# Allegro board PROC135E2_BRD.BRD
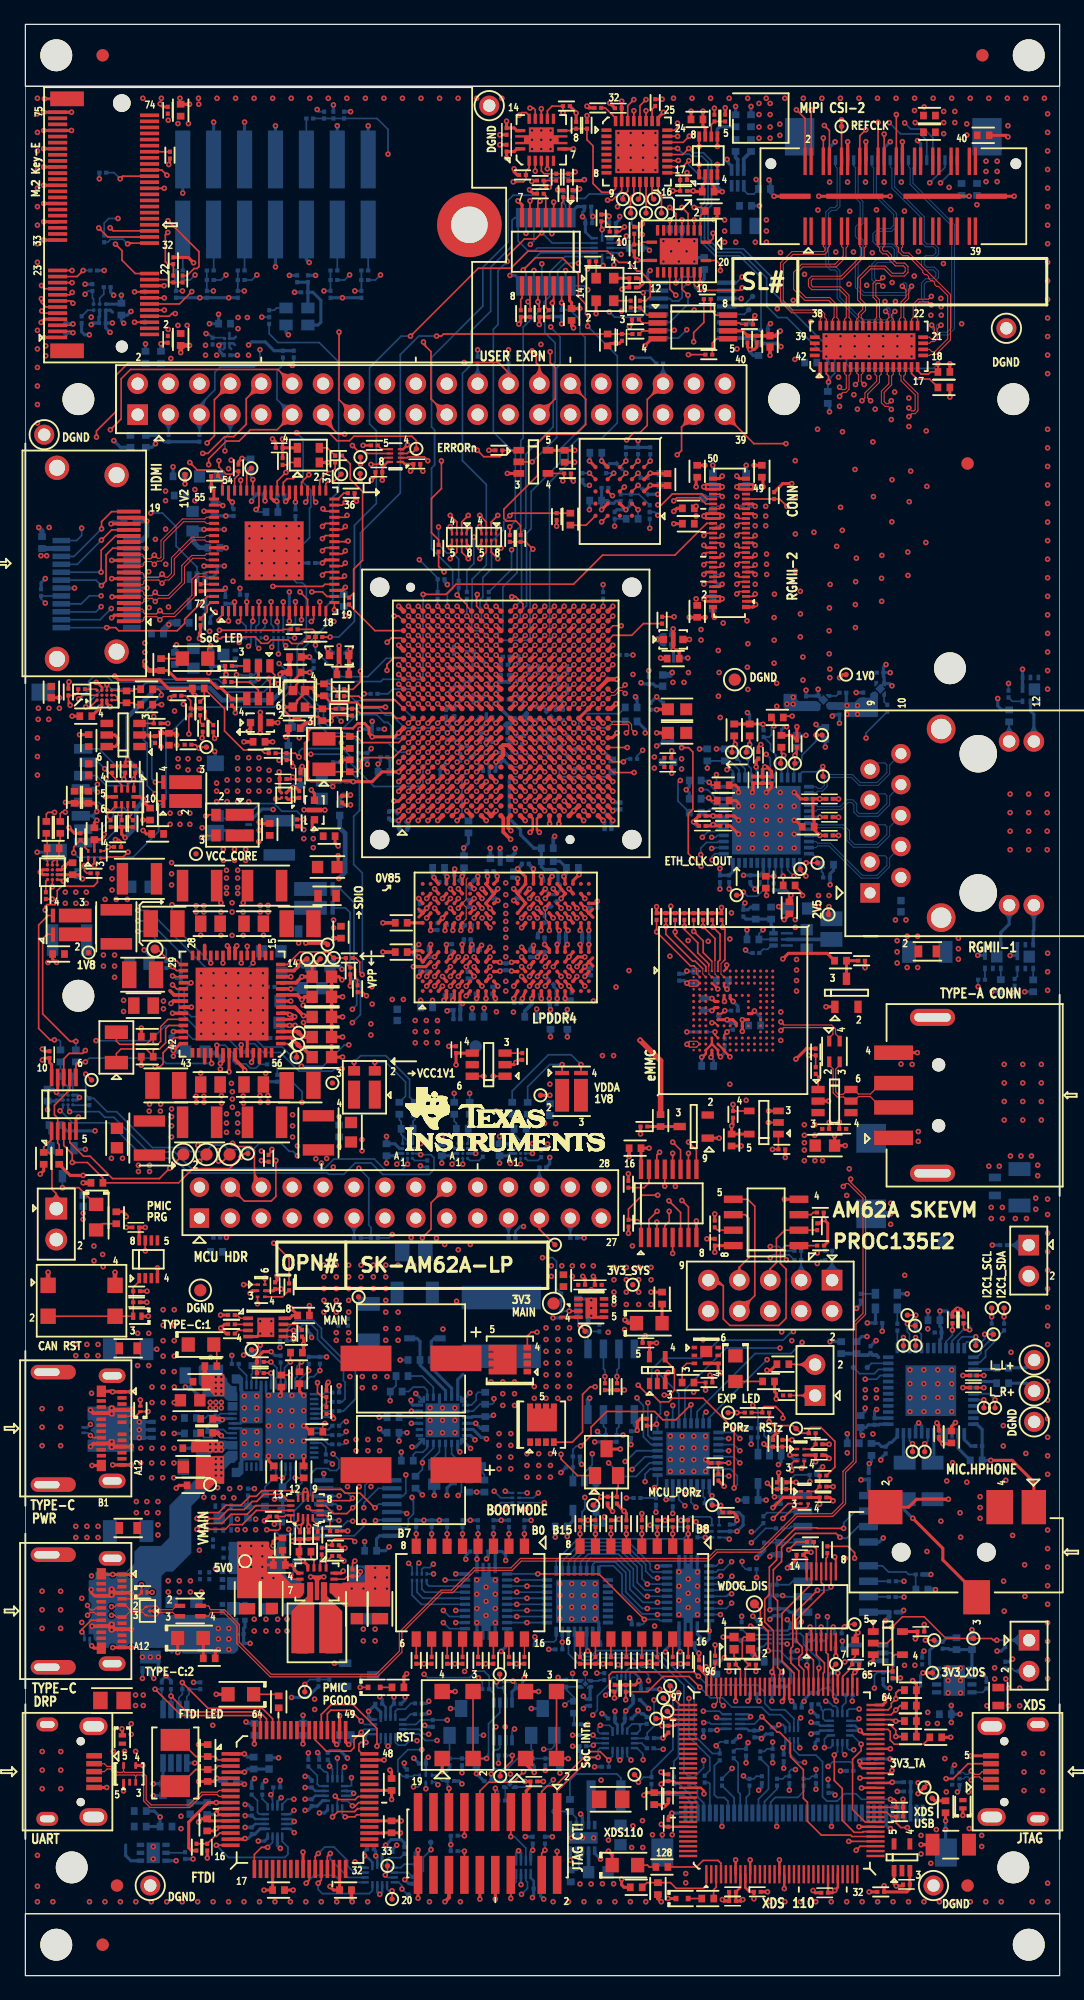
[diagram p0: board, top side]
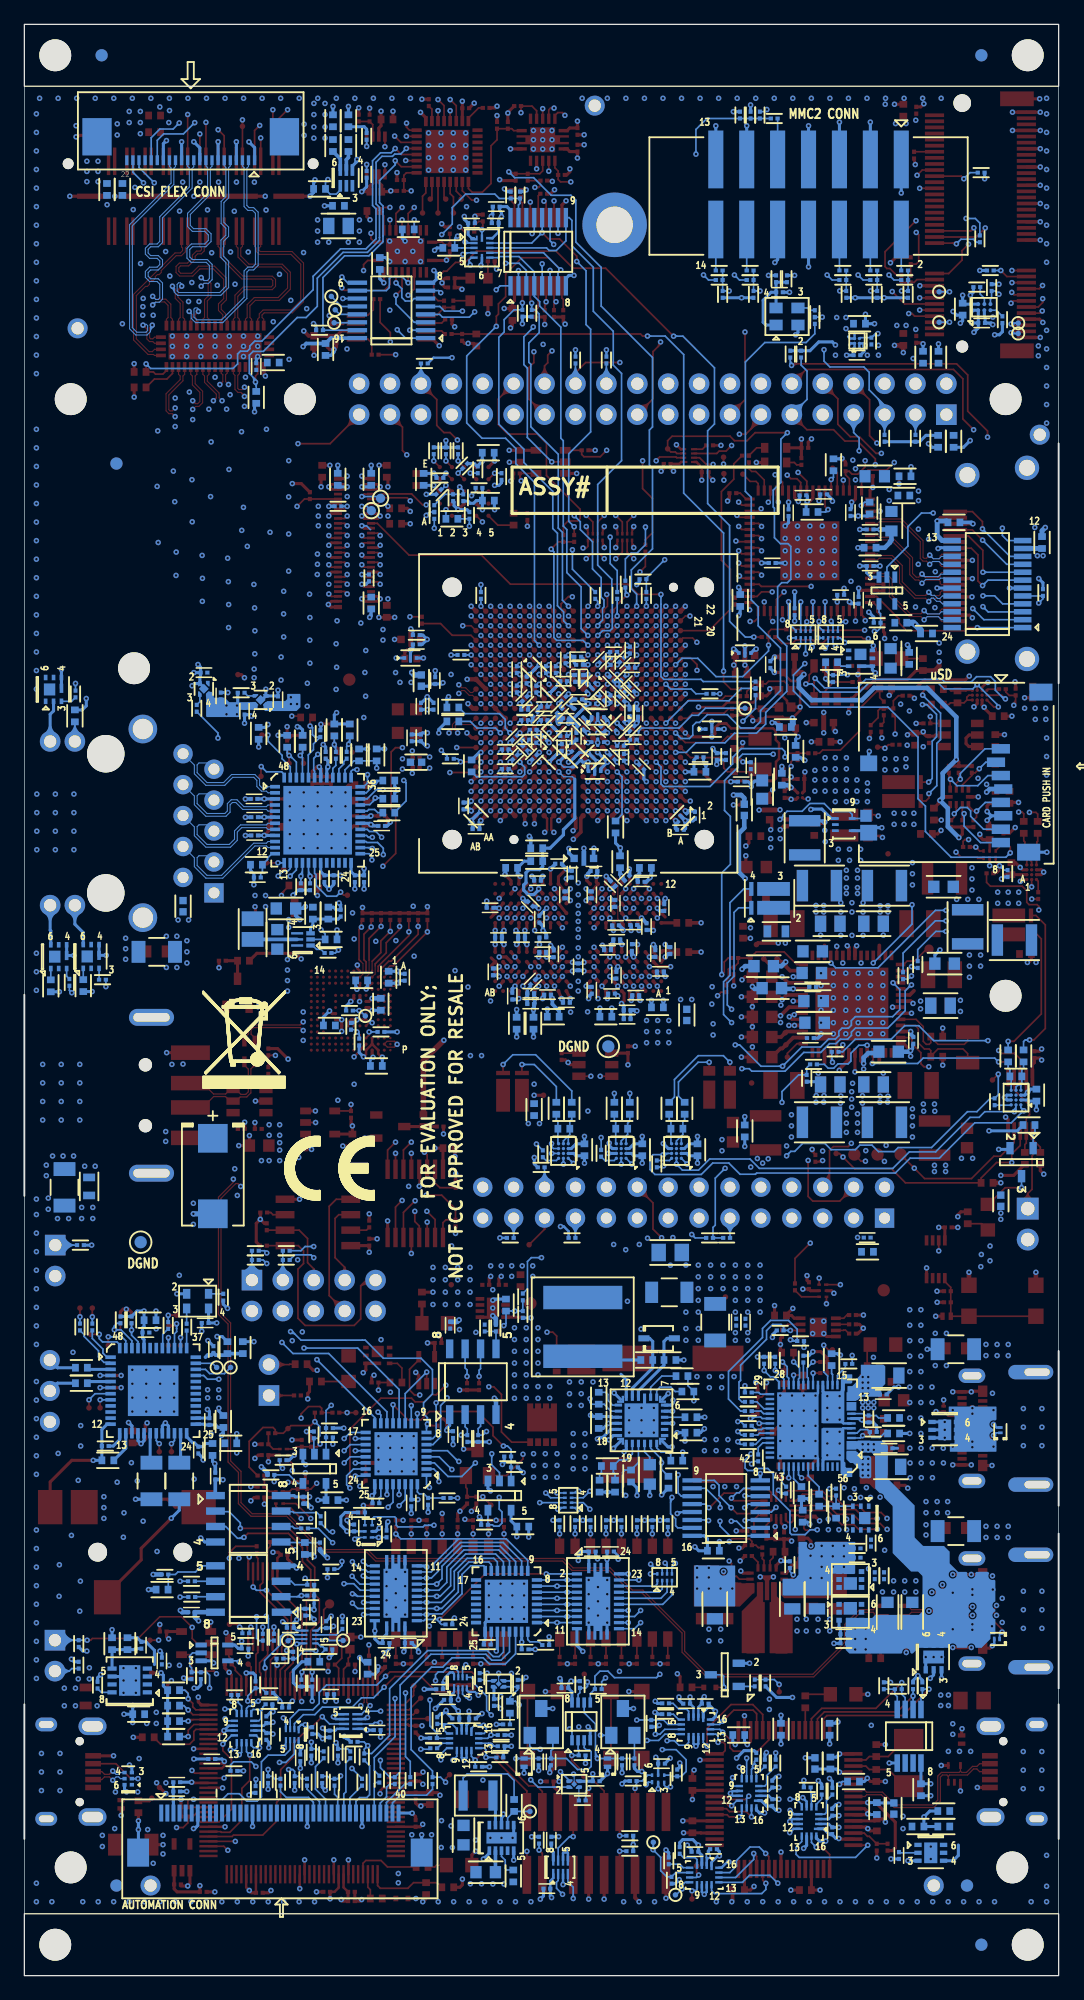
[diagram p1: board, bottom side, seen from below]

Outline 85 x 160.26 mm; copper layers: TOP, L02_GND01, L03_SIG01, L04_GND02, L05_SIG02, L06_PWR01, L07_PWR02, L08_PWR03, L09_GND03, L10_SIG03, L11_GND04, BOTTOM. Coordinates in mm from the lower left corner of the outline.
Outline path: rectangle 0,155.18 85,160.26 ; rectangle 0,0 85,5.08 ; 0,155.18 0,5.08 85,5.08 85,155.18 0,155.18

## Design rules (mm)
net group CPSW_ETH_DIFF: nets CPSW_ETH1_D0N CPSW_ETH1_D0P
net group CPSW_RGMII1_RXC: nets CPSW_RGMII1_RXC N17167245
net group CPSW_RGMII1_TXC: nets CPSW_RGMII1_TXC CPSW_RGMII_TXC_R
net group CPSW_RGMII2_TXC: nets CPSW_RGMII2_TXC CPSW_RGMII2_TXC_R
net group CSI0_MIPI_RX: nets CSI0_MIPI_RXN3 CSI0_MIPI_RXP3
net group HDMI_PCLK: nets HDMI_PCLK SOC_VOUT0_PCLK
net group MMC0_CLK: nets MMC0_CLK SOC_MMC0_CLK
net group MMC1_CLK_R: nets MMC1_CLK MMC1_CLK_R
net group MMC2_CLK: nets MMC2_CLK SOC_MMC2_CLK
net group OSPI0_CSN0: nets OSPI0_CSN0 OSPI_CS
net group OSPI_CLK: nets N16960546 OSPI_CLK
net group SOC_OSPI_DQ0: nets OSPI_DQ0 SOC_OSPI_DQ0
net group SOC_OSPI_DQ1: nets OSPI_DQ1 SOC_OSPI_DQ1
net group SOC_OSPI_DQ2: nets OSPI_DQ2 SOC_OSPI_DQ2
net group SOC_OSPI_DQ3: nets OSPI_DQ3 SOC_OSPI_DQ3
net group SOC_OSPI_DQ4: nets OSPI_DQ4 SOC_OSPI_DQ4
net group SOC_OSPI_DQ5: nets OSPI_DQ5 SOC_OSPI_DQ5
net group SOC_OSPI_DQ6: nets OSPI_DQ6 SOC_OSPI_DQ6
net group SOC_OSPI_DQ7: nets OSPI_DQ7 SOC_OSPI_DQ7
net group SOC_SPI0: nets SOC_SPI0_CS0 SOC_SPI0_D0
net group SOC_USB0: nets SOC_USB0_DM SOC_USB0_DP
net group SOC_USB1_DM: nets SOC_USB1_DM USB_TYPEACONN_DM
net group SOC_USB1_DP: nets SOC_USB1_DP USB_TYPEACONN_DP
net group USBC_CONN2: nets USBC_CONN2_DM USBC_CONN2_DP
net group XDS_USB: nets XDS_USB_DM XDS_USB_DP
net group EXP_SPI0: nets EXP_SPI0_CLK EXP_SPI0_CS0 EXP_SPI0_CS1 EXP_SPI0_D0 EXP_SPI0_D1 SOC_SPI0_CLK
net group EXP_SPI2: nets EXP_SPI2_CLK EXP_SPI2_CS0/EHRPWM0_A EXP_SPI2_CS1 EXP_SPI2_CS2 EXP_SPI2_D0 EXP_SPI2_D1/ECAP2_IN_APWM_OUT
net group JTAG: nets SOC_TCK SOC_TDI SOC_TDO SOC_TDO_R SOC_TMS SOC_TRST#
net group MCU_SPI0: nets MCU_SPI0_CLK MCU_SPI0_CS1 MCU_SPI0_D0 MCU_SPI0_D1
net group MMC0_SD-CARD: nets MMC1_SDCD
net group OSPI0_LBCLK: nets OSPI0_LBCLK OSPI0_LBCLKO_R OSPI_DQS OSPI_DQS_SOC
net group PWR: nets VCC1V8_CLKBUF VCC_3V3_FT4232 VCC_5V0_FB VCC_5V0_HDMICONN VDDSHV_SDIO
net group SOC_SPI2: nets SOC_SPI2_CLK SOC_SPI2_CS0 SOC_SPI2_D0 SOC_SPI2_D1

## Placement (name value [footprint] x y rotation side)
ACC*  -  [unnamed#3]  39.48 103.67 90 top
C1  0.01uF  [CAP0201_0-5]  48.73 153.37 0 top
C2  10uF  [CAP0402_0-75]  12.76 153.21 90 top
C3  0.1uF  [CAP0201_0-5]  11.7 153.2 270 top
C4  0.1uF  [CAP0402_0-75]  74.3 152.77 180 top
C5  0.1uF  [CAP0402_0-75]  55.2 152.45 0 top
C6  0.1uF  [CAP0201_0-5]  39.54 151.47 90 top
C7  10uF  [CAP0402_0-75]  74.3 151.4 180 top
C8  0.1uF  [CAP0402_0-75]  78.72 151.14 0 top
C9  0.1uF  [CAP0201_0-5]  39.54 150.09 270 top
C10  0.1uF  [CAP0402_0-75]  56.12 146.52 0 top
C11  0.1uF  [CAP0402_0-75]  56.35 144.93 180 top
C12  0.01uF  [CAP0201_0-5]  49.91 139.41 180 top
C13  0.1uF  [CAP0402_0-75]  44.89 136.43 90 top
C14  0.1uF  [CAP0201_0-5]  59.34 134.4 90 top
C15  0.1uF  [CAP0201_0-5]  49.91 138.65 180 top
C16  1uF  [CAP0201_0-5]  60.11 134.4 90 top
C17  0.1uF  [CAP0201_0-5]  11.7 134.39 90 top
C18  10uF  [CAP0402_0-75]  12.76 134.38 270 top
C19  10pF  [CAP0201_0-5]  49.02 134.55 270 top
C20  0.1uF  [CAP0201_0-5]  20.86 125.48 0 top
C21  0.1uF  [CAP0402_0-75]  44.31 124.79 270 top
C22  0.1uF  [CAP0201_0-5]  32.17 124.16 0 top
C23  0.1uF  [CAP0402_0-75]  55.21 123.55 90 top
C24  0.1uF  [CAP0402_0-75]  60.52 123.55 90 top
C25  0.1uF  [CAP0201_0-5]  29.05 123.48 0 top
C26  4.7uF  [CAP0402_0-75]  52.78 122.87 90 top
C27  10uF  [CAP0402_0-75]  54.49 120.51 180 top
C28  0.1uF  [CAP0402_0-75]  54.49 119.24 180 top
C29  0.1uF  [CAP0402_0-75]  55.21 112.05 270 top
C30  10uF  [CAP0402_1]  53.24 108.17 0 top
C31  10uF  [CAP0402_1]  22.16 107.03 0 top
C32  10uF  [CAP0402_1]  26.09 106.87 180 top
C33  18pF  [CAP0402_0-75]  24.54 105.6 90 top
C34  0.1uF  [CAP0402_0-75]  8.31 105.02 270 top
C35  0.01uF  [CAP0201_0-5]  16.98 104.59 90 top
C36  18pF  [CAP0402_0-75]  24.41 103.55 90 top
C37  0.1uF  [CAP0402_0-75]  4.97 103.44 180 top
C38  0.1uF  [CAP0402_0-75]  11.8 101.54 90 top
C39  1uF  [CAP0201_0-5]  10.66 101.52 90 top
C40  4.7uF  [CAP0402_0-75]  5.2 101.43 90 top
C41  10uF  [CAP0402_1]  19.2 101.33 180 top
C42  9pF  [CAP0402_0-75]  26.67 101.28 270 top
C43  1uF  [CAP0201_0-5]  60.24 100.23 90 top
C44  4.7uF  [CAP0201_0-5]  52.79 100.02 0 top
C45  9pF  [CAP0402_0-75]  26.67 99.36 90 top
C46  4.7uF  [CAP0201_0-5]  52.79 99.26 0 top
C47  1uF  [CAP0201_0-5]  22.6 98.5 270 top
C48  0.01uF  [CAP0201_0-5]  59.81 98.2 270 top
C49  1uF  [CAP0201_0-5]  60.57 98.2 270 top
C50  0.1uF  [CAP0201_0-5]  61.33 98.2 270 top
C51  1uF  [CAP0201_0-5]  21.18 98.28 0 top
C52  2.2uF  [CAP0402_0-75]  4.04 96.78 90 top
C53  0.1uF  [CAP0402_0-75]  5.18 96.78 90 top
C54  0.01uF  [CAP0201_0-5]  64.45 96.64 180 top
C55  0.1uF  [CAP0201_0-5]  66.07 93.64 0 bottom
C56  1uF  [CAP0201_0-5]  26.04 96.61 270 top
C57  0.1uF  [CAP0402_0-75]  10.25 95.4 90 top
C58  0.1uF  [CAP0201_0-5]  55.63 95.25 180 top
C59  1uF  [CAP0201_0-5]  57.39 95.25 0 top
C60  0.1uF  [CAP0201_0-5]  66.07 95.14 0 top
C61  1uF  [CAP0201_0-5]  55.63 94.43 180 top
C62  0.1uF  [CAP0201_0-5]  57.39 94.43 0 top
C63  10uF  [CAP0402_0-75]  64.33 94.35 180 top
C64  0.1uF  [CAP0402_0-75]  20.08 94.14 270 top
C65  0.1uF  [CAP0402_0-75]  5.67 93.79 90 top
C66  0.1uF  [CAP0402_0-75]  10.87 93.77 0 top
C67  1uF  [CAP0201_0-5]  66.07 93.64 0 top
C68  10uF  [CAP0402_1]  24.96 93.59 0 top
C69  0.1uF  [CAP0402_0-75]  2.28 92.57 0 top
C70  22uF  [CAP0603_1]  24.82 91.05 0 top
C71  0.1uF  [CAP0402_0-75]  3.88 90.91 90 top
C72  47uF  [CAP1210_2-75]  9.38 90.08 180 top
C73  47uF  [CAP1210_2-75]  14.32 89.52 0 top
C74  47uF  [CAP1210_2-75]  19.66 89.52 180 top
C75  10uF  [CAP0402_0-75]  62.79 87.71 270 top
C76  10uF  [CAP0805_1-5]  15.21 86.4 0 top
C77  10uF  [CAP0805_1-5]  18.77 86.4 180 top
C78  47uF  [CAP1210_2-75]  7.48 86.14 90 top
C79  0.1uF  [CAP0402_0-75]  25.94 85.7 90 top
C80  0.1uF  [CAP0402_0-75]  2.73 83.9 0 top
C81  2.2uF  [CAP0603_1]  24.37 82.04 0 top
C82  2.2uF  [CAP0603_1]  24.37 80.39 0 top
C83  10uF  [CAP0805_1-5]  9.71 79.66 180 top
C84  2.2uF  [CAP0603_1]  24.37 78.74 0 top
C85  9pF  [CAP0402_0-75]  10.02 77.12 0 top
C86  2.2uF  [CAP0603_1]  24.37 77.09 0 top
C87  0.01uF  [CAP0201_0-5]  35.4 76.05 270 top
C88  0.01uF  [CAP0201_0-5]  1.99 75.64 270 top
C89  9pF  [CAP0402_0-75]  10.02 75.47 0 top
C90  0.1uF  [CAP0402_0-75]  25.79 69.37 90 bottom
C91  10uF  [CAP0805_1-5]  15.21 73.19 0 top
C92  10uF  [CAP0805_1-5]  18.77 73.19 180 top
C93  47uF  [CAP1210_2-75]  14.32 70.08 0 top
C94  47uF  [CAP1210_2-75]  19.66 70.08 180 top
C95  0.1uF  [CAP0201_0-5]  65.77 69.54 0 top
C96  0.1uF  [CAP0201_0-5]  67.17 69.54 180 top
C97  22uF  [CAP0603_1]  26.76 69.27 270 top
C98  47uF  [CAP1210_2-75]  24.08 69.22 270 top
C99  22uF  [CAP0603_1]  7.53 68.79 270 top
C100  47uF  [CAP1210_2-75]  10.2 68.79 270 top
C101  0.1uF  [CAP0402_0-75]  58.04 68.63 270 top
C102  10uF  [CAP0603_1]  65.7 68.17 0 top
C103  0.1uF  [CAP0402_0-75]  50.11 67.96 0 top
C104  0.1uF  [CAP0201_0-5]  9.07 61.45 180 top
C105  0.1uF  [CAP0201_0-5]  56.66 60.23 90 top
C106  0.1uF  [CAP0201_0-5]  47.08 56.73 0 top
C107  0.1uF  [CAP0201_0-5]  20.52 56.67 270 top
C108  10uF  [CAP0402_0-75]  44.22 57.08 90 top
C109  1uF  [CAP0201_0-5]  45.72 56.73 180 top
C110  0.1uF  [CAP0201_0-5]  9.14 55.3 180 top
C111  0.1uF  [CAP0402_0-75]  22.86 54.22 0 top
C112  0.1uF  [CAP0201_0-5]  51 51.96 0 top
C113  220pF  [CAP0402_0-75]  22.28 51.17 0 top
C114  100uF_50V  [CAPAE_FCASE_10-5]  31.69 50.69 180 top
C115  0.1uF  [CAP0201_0-5]  77.91 49.29 180 top
C116  220pF  [CAP0402_0-75]  22.53 49.11 270 top
C117  4.7uF  [CAP0402_0-75]  21.03 48.83 270 top
C118  0.1uF  [CAP0402_0-75]  14.26 48.77 180 top
C119  0.1uF  [CAP0201_0-5]  77.91 48.29 180 top
C120  10uF  [CAP0603_1]  13.54 47.25 180 top
C121  10uF  [CAP0402_0-75]  14.9 45.73 0 top
C122  4.7uF  [CAP0402_0-75]  23.95 44.67 180 top
C123  10uF  [CAP0402_0-75]  14.9 44.58 0 top
C124  0.1uF  [CAP0201_0-5]  75.07 44.5 90 top
C125  10uF  [CAP0402_0-75]  76.11 44.25 90 top
C126  0.1uF  [CAP0402_0-75]  13.43 43.32 180 top
C127  0.1uF  [CAP0201_0-5]  65.22 42.75 0 top
C128  10uF  [CAP0603_1]  13.78 41.79 180 top
C129  100uF_50V  [CAPAE_FCASE_10-5]  31.69 41.52 180 top
C130  220pF  [CAP0402_0-75]  20.42 41.37 90 top
C131  220pF  [CAP0402_0-75]  22.88 41.37 90 top
C132  0.1uF  [CAP0402_0-75]  13.78 40.27 180 top
C133  0.1uF  [CAP0201_0-5]  65.55 39.27 0 top
C134  0.1uF  [CAP0201_0-5]  48.61 39.05 90 top
C135  0.1uF  [CAP0201_0-5]  69.31 41.03 270 bottom
C136  0.1uF  [CAP0402_0-75]  22.98 34.82 180 top
C137  0.1uF  [CAP0201_0-5]  63.65 34.56 0 top
C138  10uF  [CAP0603_1]  20.25 30.96 270 top
C139  22uF  [CAP0805_1-5]  18.22 30.93 270 top
C140  10uF  [CAP0603_1]  27.24 30.12 270 top
C141  10uF  [CAP0805_1-5]  29.14 30.12 270 top
C142  0.1uF  [CAP0201_0-5]  73.59 28.26 0 top
C143  0.1uF  [CAP0201_0-5]  55.36 25.63 270 top
C144  0.1uF  [CAP0201_0-5]  68.24 25.56 180 top
C145  12pF  [CAP0201_0-5]  58.1 25.55 0 top
C146  12pF  [CAP0201_0-5]  59.75 25.55 180 top
C147  0.1uF  [CAP0201_0-5]  52.85 20.24 90 top
C148  18pF  [CAP0402_0-75]  14.99 18.49 90 top
C149  18pF  [CAP0402_0-75]  14.99 16.44 270 top
C150  0.01uF  [CAP0201_0-5]  52.85 16.26 90 top
C151  0.1uF  [CAP0201_0-5]  41.79 15.95 0 top
C152  0.1uF  [CAP0402_0-75]  30.1 15.7 270 top
C153  1uF  [CAP0201_0-5]  52.85 14.75 270 top
C154  2.2uF  [CAP0402_0-75]  51.68 14.54 270 top
C155  4.7uF  [CAP0402_0-75]  75.62 13.87 270 top
C156  0.01uF  [CAP0201_0-5]  52.85 12.51 90 top
C157  0.1uF  [CAP0402_0-75]  14.94 12.38 90 top
C158  0.1uF  [CAP0402_0-75]  30.1 12.22 90 top
C159  1000pF  [CAP1206_1-75]  76.05 10.76 0 top
C160  0.1uF  [CAP0201_0-5]  14.95 10.55 90 top
C161  0.01uF  [CAP0201_0-5]  72.41 7.49 180 top
C162  0.1uF  [CAP0402_0-75]  20.81 7.03 180 top
C163  0.1uF  [CAP0402_0-75]  26.31 7.03 180 top
C164  0.01uF  [CAP0201_0-5]  58.12 6.88 180 top
C165  0.1uF  [CAP0201_0-5]  60.15 6.88 180 top
C166  0.01uF  [CAP0201_0-5]  65.69 6.81 180 top
C167  1uF  [CAP0201_0-5]  58.12 6.12 180 top
C168  2.2uF  [CAP0402_0-75]  59.64 152.34 90 bottom
C169  0.1uF  [CAP0402_0-75]  78.21 146.7 270 bottom
C170  10uF  [CAP0402_0-75]  76.94 146.7 270 bottom
C171  0.1uF  [CAP0402_0-75]  59.18 145.35 0 bottom
C172  0.1uF  [CAP0201_0-5]  46.22 145.29 180 bottom
C173  0.1uF  [CAP0201_0-5]  48.25 143.93 0 bottom
C174  0.1uF  [CAP0201_0-5]  46.3 143.93 180 bottom
C175  10uF  [CAP0805_1-5]  59.18 143.7 0 bottom
C176  0.1uF  [CAP0402_0-75]  55.79 140.62 270 bottom
C177  0.1uF  [CAP0201_0-5]  22.94 138.25 180 bottom
C178  0.1uF  [CAP0201_0-5]  22.57 36.13 90 top
C179  2.2uF  [CAP0402_0-75]  7.89 136.86 270 bottom
C180  0.1uF  [CAP0201_0-5]  23.29 36.13 90 top
C181  1uF  [CAP0201_0-5]  6.33 135.73 180 bottom
C182  2.2uF  [CAP0402_0-75]  16.37 135.67 180 bottom
C183  0.1uF  [CAP0402_0-75]  60.25 133.56 90 bottom
C184  1uF  [CAP0201_0-5]  16.57 133.09 180 bottom
C185  0.1uF  [CAP0402_0-75]  11.14 132.92 270 bottom
C186  2.2uF  [CAP0402_0-75]  9.87 132.92 90 bottom
C187  2.2uF  [CAP0402_0-75]  64.54 132.48 180 bottom
C188  0.1uF  [CAP0201_0-5]  65.94 132.16 270 bottom
C189  0.1uF  [CAP0402_0-75]  9.9 126.01 90 bottom
C190  2.2uF  [CAP0402_0-75]  8.63 126.01 270 bottom
C191  0.1uF  [CAP0402_0-75]  46.88 125.08 180 bottom
C192  10uF  [CAP0402_0-75]  12.63 123.14 180 bottom
C193  10uF  [CAP0402_0-75]  59.24 122.89 90 bottom
C194  10uF  [CAP0402_0-75]  56.49 122.89 90 bottom
C195  0.1uF  [CAP0402_0-75]  52.18 122.89 270 bottom
C196  0.1uF  [CAP0201_0-5]  19.31 121.66 180 bottom
C197  0.1uF  [CAP0201_0-5]  21.01 121.58 0 bottom
C198  4.7uF  [CAP0402_0-75]  12.72 121.56 180 bottom
C199  0.1uF  [CAP0402_0-75]  46.86 121.15 180 bottom
C200  0.1uF  [CAP0201_0-5]  17.11 120.16 270 bottom
C201  0.1uF  [CAP0201_0-5]  22.2 120.15 270 bottom
C202  10uF  [CAP0402_0-75]  8.6 119.36 180 bottom
C203  0.1uF  [CAP0201_0-5]  15.49 118.77 0 bottom
C204  10uF  [CAP0402_0-75]  1.37 117.7 90 bottom
C205  10uF  [CAP0402_0-75]  15.49 117.27 0 bottom
C206  0.1uF  [CAP0201_0-5]  23.54 116.02 180 bottom
C207  0.1uF  [CAP0201_0-5]  15.49 115.77 0 bottom
C208  0.1uF  [CAP0201_0-5]  17.91 113.41 180 bottom
C209  10uF  [CAP0402_0-75]  56.49 112.73 270 bottom
C210  0.1uF  [CAP0201_0-5]  16.44 112.96 90 bottom
C211  10uF  [CAP0402_0-75]  26.17 112.94 270 bottom
C212  0.1uF  [CAP0201_0-5]  21.69 112.02 90 bottom
C213  10uF  [CAP0402_0-75]  10.86 110.23 180 bottom
C214  1uF  [CAP0201_0-5]  52.78 110.1 0 bottom
C215  1uF  [CAP0201_0-5]  52.78 109.34 0 bottom
C216  0.1uF  [CAP0201_0-5]  35.23 108.86 270 bottom
C217  0.1uF  [CAP0201_0-5]  36.58 108.72 0 bottom
C218  0.1uF  [CAP0201_0-5]  39.52 108.32 0 bottom
C219  10uF  [CAP0402_0-75]  12.29 108.18 90 bottom
C220  1uF  [CAP0201_0-5]  40.53 108.07 90 bottom
C221  1uF  [CAP0201_0-5]  35.88 108.07 135 bottom
C222  1uF  [CAP0201_0-5]  37.54 108.03 135 bottom
C223  1uF  [CAP0201_0-5]  36.82 107.93 90 bottom
C224  1uF  [CAP0201_0-5]  23.69 107.67 270 bottom
C225  0.1uF  [CAP0201_0-5]  39.37 107.66 0 bottom
C226  0.1uF  [CAP0201_0-5]  35.08 107.42 180 bottom
C227  0.1uF  [CAP0201_0-5]  44.53 107.26 90 bottom
C228  0.1uF  [CAP0201_0-5]  42.13 107.26 270 bottom
C229  0.1uF  [CAP0201_0-5]  41.33 107.26 90 bottom
C230  1uF  [CAP0201_0-5]  70.24 107.02 0 bottom
C231  1uF  [CAP0201_0-5]  35.78 106.57 315 bottom
C232  0.1uF  [CAP0201_0-5]  39.73 106.54 270 bottom
C233  1uF  [CAP0201_0-5]  39.08 106.54 270 bottom
C234  1uF  [CAP0201_0-5]  36.73 106.52 225 bottom
C235  1uF  [CAP0201_0-5]  43.73 106.41 90 bottom
C236  1uF  [CAP0201_0-5]  51.23 106.36 90 bottom
C237  0.1uF  [CAP0201_0-5]  40.68 106.31 0 bottom
C238  0.1uF  [CAP0201_0-5]  44.53 105.67 90 bottom
C239  1uF  [CAP0201_0-5]  42.93 105.67 90 bottom
C240  0.1uF  [CAP0201_0-5]  35.08 105.67 225 bottom
C241  1uF  [CAP0201_0-5]  35.83 105.61 45 bottom
C242  1uF  [CAP0201_0-5]  68.86 105.1 90 bottom
C243  0.1uF  [CAP0201_0-5]  37.53 104.92 225 bottom
C244  0.1uF  [CAP0201_0-5]  43.88 104.87 315 bottom
C245  0.1uF  [CAP0201_0-5]  40.68 104.86 315 bottom
C246  0.1uF  [CAP0201_0-5]  36.83 104.86 270 bottom
C247  0.1uF  [CAP0201_0-5]  35.88 104.86 225 bottom
C248  0.1uF  [CAP0201_0-5]  39.45 104.81 180 bottom
C249  1uF  [CAP0201_0-5]  64.16 104.79 90 bottom
C250  0.1uF  [CAP0201_0-5]  38.28 104.47 0 bottom
C251  4.7uF  [CAP0201_0-5]  52.41 104.26 90 bottom
C252  1uF  [CAP0201_0-5]  51.37 104.26 90 bottom
C253  1uF  [CAP0201_0-5]  42.28 104.22 0 bottom
C254  0.1uF  [CAP0201_0-5]  43.88 103.96 0 bottom
C255  2.2uF  [CAP0201_0-5]  41 103.88 135 bottom
C256  1uF  [CAP0201_0-5]  66.9 103.85 270 bottom
C257  0.1uF  [CAP0201_0-5]  35.26 103.72 90 bottom
C258  1uF  [CAP0201_0-5]  34.57 103.67 270 bottom
C259  0.1uF  [CAP0201_0-5]  43.01 103.6 135 bottom
C260  1uF  [CAP0201_0-5]  40.48 103.26 180 bottom
C261  0.1uF  [CAP0201_0-5]  43.88 103.11 0 bottom
C262  0.1uF  [CAP0201_0-5]  42.28 103.11 180 bottom
C263  1uF  [CAP0201_0-5]  39.25 102.53 45 bottom
C264  1uF  [CAP0201_0-5]  35.06 102.44 135 bottom
C265  0.1uF  [CAP0201_0-5]  37.43 102.41 45 bottom
C266  0.1uF  [CAP0201_0-5]  43.18 102.32 180 bottom
C267  10uF  [CAP0402_0-75]  65.74 102.03 90 bottom
C268  0.1uF  [CAP0201_0-5]  40.68 101.82 0 bottom
C269  0.1uF  [CAP0201_0-5]  39.63 101.79 90 bottom
C270  1uF  [CAP0201_0-5]  44.69 101.68 315 bottom
C271  1uF  [CAP0201_0-5]  53.17 101.66 270 bottom
C272  4.7uF  [CAP0201_0-5]  52.41 101.66 270 bottom
C273  1uF  [CAP0201_0-5]  42.22 101.6 45 bottom
C274  0.1uF  [CAP0201_0-5]  42.93 101.54 90 bottom
C275  0.1uF  [CAP0201_0-5]  43.78 101.51 0 bottom
C276  0.1uF  [CAP0201_0-5]  34.95 101.51 0 bottom
C277  0.1uF  [CAP0201_0-5]  36.01 101.02 180 bottom
C278  0.1uF  [CAP0201_0-5]  40.83 100.86 270 bottom
C279  0.1uF  [CAP0201_0-5]  43.84 100.8 45 bottom
C280  10uF  [CAP0402_1]  21.61 100.55 270 bottom
C281  0.1uF  [CAP0201_0-5]  60.24 100.23 90 bottom
C282  1uF  [CAP0201_0-5]  28.1 100.13 90 bottom
C283  0.1uF  [CAP0201_0-5]  27.34 100.13 90 bottom
C284  0.1uF  [CAP0201_0-5]  44.68 100.07 315 bottom
C285  1uF  [CAP0201_0-5]  43.08 100.07 315 bottom
C286  0.1uF  [CAP0201_0-5]  36.68 100.07 225 bottom
C287  1uF  [CAP0201_0-5]  35.73 100.07 270 bottom
C288  1uF  [CAP0201_0-5]  29.47 100.06 0 bottom
C289  4.7uF  [CAP0201_0-5]  25.29 99.37 90 bottom
C290  1uF  [CAP0201_0-5]  34.28 99.26 225 bottom
C291  10uF  [CAP0402_1]  29.48 98.87 0 bottom
C292  1uF  [CAP0201_0-5]  26.09 98.06 0 bottom
C293  0.1uF  [CAP0201_0-5]  66.12 96.64 0 bottom
C294  0.1uF  [CAP0201_0-5]  48.91 96.07 90 bottom
C295  0.1uF  [CAP0201_0-5]  29.89 95.31 270 bottom
C296  1uF  [CAP0201_0-5]  66.07 95.14 0 bottom
C297  0.01uF  [CAP0201_0-5]  55.63 94.43 180 bottom
C298  0.1uF  [CAP0201_0-5]  47.88 94.16 0 bottom
C299  0.1uF  [CAP0201_0-5]  31.08 94.11 180 bottom
C300  1uF  [CAP0201_0-5]  66.07 96.64 0 top
C301  47uF  [CAP1210_2-75]  20.87 93.45 90 bottom
C302  10uF  [CAP0402_0-75]  36.05 91.48 90 bottom
C303  0.1uF  [CAP0201_0-5]  41.09 91.33 180 bottom
C304  10uF  [CAP0402_0-75]  44.96 90.98 0 bottom
C305  10uF  [CAP0402_0-75]  33.96 90.98 180 bottom
C306  1000pF  [CAP0201_0-5]  38.19 90.72 180 bottom
C307  22pF  [CAP0201_0-5]  65.85 90.19 180 bottom
C308  0.01uF  [CAP0201_0-5]  40 90.47 270 bottom
C309  0.1uF  [CAP0201_0-5]  35.46 90.13 135 bottom
C310  0.1uF  [CAP0201_0-5]  60.34 90.09 270 bottom
C311  1uF  [CAP0201_0-5]  59.58 90.09 270 bottom
C312  1uF  [CAP0201_0-5]  57.84 90.09 270 bottom
C313  0.1uF  [CAP0201_0-5]  57.08 90.09 270 bottom
C314  0.01uF  [CAP0201_0-5]  42.83 89.93 0 bottom
C315  1000pF  [CAP0201_0-5]  34.3 89.84 180 bottom
C316  0.01uF  [CAP0201_0-5]  36.61 89.7 45 bottom
C317  47uF  [CAP1210_2-75]  19.66 89.52 180 bottom
C318  47uF  [CAP1210_2-75]  14.32 89.52 0 bottom
C319  22uF  [CAP0603_1]  9.46 89.43 180 bottom
C320  0.1uF  [CAP0201_0-5]  40.62 88.76 90 bottom
C321  0.1uF  [CAP0201_0-5]  38.36 88.76 90 bottom
C322  0.1uF  [CAP0201_0-5]  36.43 88.07 90 bottom
C323  0.1uF  [CAP0201_0-5]  43.41 88.02 45 bottom
C324  0.1uF  [CAP0201_0-5]  32.41 87.72 90 bottom
C325  0.1uF  [CAP0201_0-5]  46.72 87.7 0 bottom
C326  22uF  [CAP0603_1]  63.5 87.64 180 bottom
C327  120pF  [CAP0201_0-5]  59 87.26 270 bottom
C328  0.1uF  [CAP0201_0-5]  42.67 86.77 270 bottom
C329  10uF  [CAP0805_1-5]  18.77 86.4 180 bottom
C330  10uF  [CAP0805_1-5]  15.21 86.4 0 bottom
C331  0.1uF  [CAP0201_0-5]  34.91 86.29 0 bottom
C332  0.1uF  [CAP0201_0-5]  36.41 86.27 0 bottom
C333  0.1uF  [CAP0201_0-5]  33.87 86.16 90 bottom
C334  47uF  [CAP1210_2-75]  7.48 86.14 90 bottom
C335  0.1uF  [CAP0201_0-5]  42.39 85.27 180 bottom
C336  0.1uF  [CAP0201_0-5]  46.03 85.26 0 bottom
C337  0.1uF  [CAP0201_0-5]  44.14 85.26 180 bottom
C338  0.01uF  [CAP0201_0-5]  36.31 85.11 180 bottom
C339  4.7uF  [CAP0603_1]  64.21 85.1 90 bottom
C340  47uF  [CAP1210_2-75]  3.63 85.05 180 bottom
C341  1000pF  [CAP0201_0-5]  35.07 84.43 270 bottom
C342  0.1uF  [CAP0201_0-5]  37.07 84.22 180 bottom
C343  0.1uF  [CAP0201_0-5]  31.9 84.19 90 bottom
C344  2.2uF  [CAP0603_1]  20.21 84.12 180 bottom
C345  1000pF  [CAP0201_0-5]  42.4 84.09 180 bottom
C346  1000pF  [CAP1206_1-75]  74.12 84.08 180 bottom
C347  0.1uF  [CAP0201_0-5]  33.14 83.94 270 bottom
C348  0.1uF  [CAP0201_0-5]  41.49 83.92 270 bottom
C349  22uF  [CAP0603_1]  9.37 83.12 0 bottom
C350  2.2uF  [CAP0603_1]  24.24 82.91 0 bottom
C351  0.1uF  [CAP0201_0-5]  39.49 82.85 90 bottom
C352  0.1uF  [CAP0201_0-5]  32.73 82.48 180 bottom
C353  0.1uF  [CAP0201_0-5]  46.49 82.44 270 bottom
C354  2.2uF  [CAP0603_1]  20.28 82.35 180 bottom
C355  0.1uF  [CAP0201_0-5]  36.34 82.17 270 bottom
C356  1uF  [CAP0201_0-5]  53.73 82 90 bottom
C357  0.1uF  [CAP0402_0-75]  55.06 82 90 bottom
C358  0.1uF  [CAP0402_0-75]  57.28 81.74 180 bottom
C359  0.1uF  [CAP0201_0-5]  43.2 81.6 315 bottom
C360  0.1uF  [CAP0201_0-5]  20.21 81.21 180 bottom
C361  2.2uF  [CAP0603_1]  23.57 81.1 0 bottom
C362  0.1uF  [CAP0201_0-5]  38.37 80.93 90 bottom
C363  1000pF  [CAP0201_0-5]  43.39 80.68 0 bottom
C364  0.1uF  [CAP0201_0-5]  36.74 80.66 180 bottom
C365  1000pF  [CAP0201_0-5]  42 80.57 0 bottom
C366  0.1uF  [CAP0201_0-5]  34.76 80.52 0 bottom
C367  0.1uF  [CAP0201_0-5]  44.9 80.45 90 bottom
C368  2.2uF  [CAP0603_1]  20.14 80.04 180 bottom
C369  0.01uF  [CAP0201_0-5]  40.45 79.9 180 bottom
C370  0.1uF  [CAP0201_0-5]  43.39 79.8 0 bottom
C371  0.1uF  [CAP0402_0-75]  55.7 79.78 270 bottom
C372  10uF  [CAP0805_1-5]  9.71 79.66 180 bottom
C373  10uF  [CAP0402_0-75]  32.97 79.52 180 bottom
C374  0.1uF  [CAP0201_0-5]  35.46 79.31 180 bottom
C375  0.01uF  [CAP0201_0-5]  35.46 78.55 0 bottom
C376  2.2uF  [CAP0603_1]  20.05 78.26 180 bottom
C377  10uF  [CAP0402_0-75]  44.54 78.22 270 bottom
C378  10uF  [CAP0402_0-75]  43.16 78.22 270 bottom
C379  2.2uF  [CAP0402_0-75]  59.93 78.04 0 bottom
C380  0.1uF  [CAP0201_0-5]  20.4 77 180 bottom
C381  0.1uF  [CAP0201_0-5]  11.94 76.81 270 bottom
C382  2.2uF  [CAP0603_1]  24.37 75.44 0 top
C383  2.2uF  [CAP0603_1]  13.97 75.88 180 bottom
C384  2.2uF  [CAP0402_0-75]  56.07 74.71 0 bottom
C385  0.1uF  [CAP0402_0-75]  3.52 73.86 180 bottom
C386  10uF  [CAP0805_1-5]  18.77 73.19 180 bottom
C387  10uF  [CAP0805_1-5]  15.21 73.19 0 bottom
C388  0.1uF  [CAP0402_0-75]  1.83 72.32 90 bottom
C389  0.1uF  [CAP0402_0-75]  43.11 71.13 90 bottom
C390  47uF  [CAP1210_2-75]  19.66 70.08 180 bottom
C391  47uF  [CAP1210_2-75]  14.32 70.08 0 bottom
C392  0.1uF  [CAP0402_0-75]  40.66 69.56 180 bottom
C393  0.1uF  [CAP0402_0-75]  35.91 69.56 180 bottom
C394  0.1uF  [CAP0402_0-75]  31.37 69.56 180 bottom
C395  0.1uF  [CAP0402_0-75]  38.97 67.83 90 bottom
C396  0.1uF  [CAP0402_0-75]  34.22 67.83 90 bottom
C397  0.1uF  [CAP0402_0-75]  29.68 67.83 90 bottom
C398  150uF_10V  [CAPT7343D_3-25]  69.51 65.67 270 bottom
C399  1000pF  [CAP1206_1-75]  81.7 64.74 270 bottom
C400  1uF  [CAP0201_0-5]  15.73 60.62 0 bottom
C401  0.1uF  [CAP0402_0-75]  15.71 59.45 180 bottom
C402  10uF  [CAP0402_0-75]  74.67 53.83 180 bottom
C403  47uF  [CAP1206_2]  28.23 53.67 270 bottom
C404  0.1uF  [CAP0201_0-5]  26.5 53.67 90 bottom
C405  0.1uF  [CAP0201_0-5]  25.74 53.67 90 bottom
C406  0.1uF  [CAP0201_0-5]  70.14 53.61 0 bottom
C407  0.1uF  [CAP0201_0-5]  75.01 52.82 180 bottom
C408  0.1uF  [CAP0201_0-5]  50.01 53.42 90 bottom
C409  10uF  [CAP0402_0-75]  68.31 51.58 90 bottom
C410  1000pF  [CAP1206_1-75]  8.45 51.45 0 bottom
C411  0.1uF  [CAP0201_0-5]  69.46 51.42 90 bottom
C412  0.1uF  [CAP0402_0-75]  33.85 50.56 180 bottom
C413  2.2uF  [CAP0402_0-75]  31.94 50.56 180 bottom
C414  0.1uF  [CAP0402_0-75]  80.31 49.93 180 bottom
C415  1uF  [CAP0805_1-5]  13.93 49.28 180 bottom
C416  0.1uF  [CAP0402_0-75]  80.31 48.66 180 bottom
C417  0.01uF  [CAP0201_0-5]  14.42 47.73 180 bottom
C418  0.1uF  [CAP0201_0-5]  69.79 45.51 90 bottom
C419  10uF  [CAP0402_0-75]  68.64 45.51 90 bottom
C420  0.1uF  [CAP0402_0-75]  37.79 45.43 270 bottom
C421  0.1uF  [CAP0402_0-75]  30.22 44.59 0 bottom
C422  0.1uF  [CAP0201_0-5]  49.77 44.43 270 bottom
C423  0.01uF  [CAP0201_0-5]  13.93 43.31 180 bottom
C424  10uF  [CAP0402_0-75]  69.53 43.22 270 bottom
C425  0.1uF  [CAP0201_0-5]  70.7 43.16 270 bottom
C426  0.47uF  [CAP0402_0-75]  78.14 42.32 180 bottom
C427  0.22uF  [CAP0402_0-75]  31.38 42.29 180 bottom
C428  1uF  [CAP0805_1-5]  13.78 41.79 180 bottom
C429  0.12uF  [CAP0603_1]  33.6 41.17 270 bottom
C430  47uF  [CAP1206_2]  74.55 40.63 270 bottom
C431  47uF  [CAP1206_2]  72.27 40.63 270 bottom
C432  0.015uF  [CAP0402_0-75]  37.72 40.2 270 bottom
C433  330pF  [CAP0402_0-75]  36.45 40.2 270 bottom
C434  0.1uF  [CAP0402_0-75]  59.72 39.06 180 bottom
C435  0.01uF  [CAP0201_0-5]  53.2 38.82 90 bottom
C436  4.7uF  [CAP0402_0-75]  21.03 37.73 270 bottom
C437  0.1uF  [CAP0201_0-5]  62.07 39.04 90 bottom
C438  0.1uF  [CAP0402_0-75]  44.04 36.88 180 bottom
C439  0.1uF  [CAP0201_0-5]  57.89 36.77 270 bottom
C440  1000pF  [CAP1206_1-75]  8.45 36.51 0 bottom
C441  0.1uF  [CAP0402_0-75]  28.37 34.9 0 bottom
C442  0.1uF  [CAP0201_0-5]  38.33 34.83 0 bottom
C443  0.1uF  [CAP0201_0-5]  36.83 34.83 180 bottom
C444  0.1uF  [CAP0201_0-5]  16.56 34.33 180 bottom
C445  0.1uF  [CAP0201_0-5]  15.11 32.84 90 bottom
C446  22uF  [CAP0805_1-5]  21.89 30.92 270 bottom
C447  22uF  [CAP0805_1-5]  19.86 30.92 270 bottom
C448  10uF  [CAP0805_1-5]  28.25 30.11 270 bottom
C449  10uF  [CAP0603_1]  14.06 29.86 90 bottom
C450  10uF  [CAP0603_1]  12.03 29.86 90 bottom
C451  0.1uF  [CAP0201_0-5]  71.27 29.85 180 bottom
C452  0.1uF  [CAP0201_0-5]  61.92 29.85 90 bottom
C453  0.1uF  [CAP0201_0-5]  60.2 28.83 270 bottom
C454  0.1uF  [CAP0201_0-5]  63.14 28.57 180 bottom
C455  0.1uF  [CAP0201_0-5]  17.65 28.05 0 bottom
C456  0.1uF  [CAP0201_0-5]  55.28 27.32 180 bottom
C457  0.1uF  [CAP0201_0-5]  53.44 27.32 0 bottom
C458  15pF  [CAP0201_0-5]  75.38 27.14 270 bottom
C459  0.1uF  [CAP0201_0-5]  66.86 26.87 0 bottom
C460  0.01uF  [CAP0201_0-5]  43.85 26.8 0 bottom
C461  1uF  [CAP0201_0-5]  73.7 25.84 90 bottom
C462  0.1uF  [CAP0201_0-5]  40.58 23.61 180 bottom
C463  0.1uF  [CAP0201_0-5]  50.87 23.52 180 bottom
C464  0.1uF  [CAP0201_0-5]  59.83 23.12 180 bottom
C465  0.1uF  [CAP0201_0-5]  50.23 22.65 180 bottom
C466  0.01uF  [CAP0201_0-5]  46.41 22.44 90 bottom
C467  0.1uF  [CAP0201_0-5]  30.57 22.34 180 bottom
C468  0.1uF  [CAP0201_0-5]  29.05 22.34 0 bottom
C469  1uF  [CAP0201_0-5]  63.53 22.01 0 bottom
C470  2.2uF  [CAP0402_0-75]  75.6 21.47 0 bottom
C471  0.1uF  [CAP0201_0-5]  49.54 21.12 180 bottom
C472  0.1uF  [CAP0201_0-5]  48.17 21.12 0 bottom
C473  0.1uF  [CAP0201_0-5]  65.11 21.02 270 bottom
C474  8.2pF  [CAP0201_0-5]  45.37 20.64 0 bottom
C475  0.1uF  [CAP0402_0-75]  22.82 20.23 270 bottom
C476  0.1uF  [CAP0402_0-75]  18.82 20.23 270 bottom
C477  0.1uF  [CAP0201_0-5]  56.01 20.17 0 bottom
C478  0.1uF  [CAP0201_0-5]  61.34 20.13 90 bottom
C479  0.1uF  [CAP0201_0-5]  59.91 19.85 90 bottom
C480  4.7uF  [CAP0402_0-75]  26.29 19.76 180 bottom
C481  0.1uF  [CAP0201_0-5]  65.11 19.64 90 bottom
C482  0.1uF  [CAP0201_0-5]  62.32 17.89 90 bottom
C483  0.1uF  [CAP0201_0-5]  69.6 17.79 180 bottom
C484  0.1uF  [CAP0201_0-5]  41.72 17.55 90 bottom
C485  0.1uF  [CAP0201_0-5]  34.86 17.55 90 bottom
C486  0.1uF  [CAP0402_0-75]  18.76 17.46 270 bottom
C487  0.1uF  [CAP0201_0-5]  32.63 17.41 0 bottom
C488  0.01uF  [CAP0201_0-5]  38.01 15.97 0 bottom
C489  0.1uF  [CAP0201_0-5]  72.48 15.89 180 bottom
C490  0.1uF  [CAP0201_0-5]  23.53 15.73 270 bottom
C491  0.1uF  [CAP0402_0-75]  11.31 15.27 90 bottom
C492  0.1uF  [CAP0201_0-5]  72.48 15.12 180 bottom
C493  0.1uF  [CAP0201_0-5]  23.53 14.21 90 bottom
C494  0.1uF  [CAP0402_0-75]  14.94 13.72 90 bottom
C495  0.1uF  [CAP0402_0-75]  9.44 13.52 180 bottom
C496  0.1uF  [CAP0201_0-5]  18.61 13.42 270 bottom
C497  2.2uF  [CAP0402_0-75]  11.56 12.25 180 bottom
C498  10uF  [CAP0402_0-75]  9.44 12.25 180 bottom
C499  0.1uF  [CAP0201_0-5]  18.61 11.9 90 bottom
C500  22uF  [CAP0603_1]  48.91 11.54 270 bottom
C501  0.1uF  [CAP0201_0-5]  41.69 11.12 270 bottom
C502  0.1uF  [CAP0201_0-5]  28.36 10.39 0 bottom
C503  0.1uF  [CAP0201_0-5]  29.88 10.17 180 bottom
C504  0.01uF  [CAP0201_0-5]  13.12 9.87 90 bottom
C505  4.7uF  [CAP0603_1]  47.08 8.49 0 bottom
C506  0.1uF  [CAP0201_0-5]  42.05 7.15 180 bottom
C507  1uF  [CAP0201_0-5]  22.52 97.01 270 top
C508  1uF  [EMIFIL_NFM15CC_0402_0-5]  41.48 105.67 225 bottom
C509  1uF  [EMIFIL_NFM15CC_0402_0-5]  39.42 103.7 45 bottom
C510  1uF  [EMIFIL_NFM15CC_0402_0-5]  37.88 103.37 0 bottom
C511  1uF  [EMIFIL_NFM15CC_0402_0-5]  38.43 105.82 315 bottom
C512  1uF  [EMIFIL_NFM15CC_0402_0-5]  43.08 107.26 225 bottom
C513  1uF  [EMIFIL_NFM15CC_0402_0-5]  37.88 101.3 180 bottom
C514  1uF  [EMIFIL_NFM15CC_0402_0-5]  41.48 102.47 135 bottom
C515  10uF  [EMIFIL_NFM18C_0603_0-7]  53.24 109.74 0 top
C516  1uF  [EMIFIL_NFM15CC_0402_0-5]  53.27 108.22 180 bottom
C517  10uF  [EMIFIL_NFM18C_0603_0-7]  39.02 91.76 180 bottom
C518  1uF  [EMIFIL_NFM15CC_0402_0-5]  38.13 98.92 180 bottom
C519  1uF  [EMIFIL_NFM15CC_0402_0-5]  38.28 100.07 135 bottom
C520  1uF  [EMIFIL_NFM15CC_0402_0-5]  41.48 100.07 225 bottom
C521  1uF  [EMIFIL_NFM15CC_0402_0-5]  39.64 100.2 225 bottom
C522  10uF  [EMIFIL_NFM18C_0603_0-7]  19.31 102.91 0 top
C523  1uF  [EMIFIL_NFM15CC_0402_0-5]  36.03 102.62 315 bottom
C524  1uF  [EMIFIL_NFM15CC_0402_0-5]  47.88 95.26 225 bottom
C525  1uF  [EMIFIL_NFM15CC_0402_0-5]  30.92 95.11 315 bottom
C526  10uF  [EMIFIL_NFM18C_0603_0-7]  23.76 95.73 90 top
C527  1uF  [EMIFIL_NFM15CC_0402_0-5]  28.5 102.38 180 bottom
C528  10uF  [EMIFIL_NFM18C_0603_0-7]  25.78 108.42 0 top
C529  1uF  [EMIFIL_NFM15CC_0402_0-5]  25.78 108.62 180 bottom
C530  0.1uF  [CAP0402_0-75]  12.97 111.11 0 bottom
D1  BZX84C6V8LT1G  [SOT23-123_1-2]  67.48 80.72 90 top
D2  BZX84C6V8LT1G  [SOT23-123_1-2]  54.93 69.74 180 top
D3  TPD1E10B06DPYR  [DIO_DFN0402_0-5]  9.2 54.16 180 top
D4  TPD1E01B04DPLT  [DIO_DFN0201_0-4]  9.45 46.55 90 top
D5  TPD1E01B04DPLT  [DIO_DFN0201_0-4]  9.77 31.48 0 top
D6  ESD122DMXR  [X2SON3_ESD122DMX_30X40_0-4]  10.04 29.95 180 top
D7  TPD1E10B06DPYR  [DIO_DFN0402_0-5]  7.97 19.39 270 top
D8  TPD1E10B06DPYR  [DIO_DFN0402_0-5]  77.05 14.08 90 top
D9  XBS104S13R  [DIO_SOD323_1]  32.83 52.34 180 bottom
D10  TPD1E01B04DPLT  [DIO_DFN0201_0-4]  4.79 44.8 90 bottom
D11  TPD1E01B04DPLT  [DIO_DFN0201_0-4]  5.07 27.65 0 bottom
D12  TPD1E10B06DPYR  [DIO_DFN0402_0-5]  43.93 17.49 90 bottom
D13  TPD1E10B06DPYR  [DIO_DFN0402_0-5]  37.07 17.49 90 bottom
FB1  300E  [IND0603]  15.11 123.14 180 bottom
FB2  300E  [IND0603]  13.74 119.45 90 bottom
FB3  300E  [IND0603]  13.81 108.18 270 bottom
FL1  120E  [EMIFIL_BLM15A_0402_0-6]  61.2 134.22 90 top
FL2  120E  [EMIFIL_BLM15A_0402_0-6]  2.14 105.41 90 top
FL3  26E  [EMIFIL_BLM18P_0603_0-8]  53.56 104 180 top
FL4  26E  [EMIFIL_BLM18P_0603_0-8]  53.56 102.07 180 top
FL5  120E  [EMIFIL_BLM15A_0402_0-6]  5.21 99.06 270 top
FL7  120E  [EMIFIL_BLM15A_0402_0-6]  52.38 106.36 270 bottom
FL8  120E  [EMIFIL_BLM15A_0402_0-6]  52.81 99.66 180 bottom
FL9  26E  [EMIFIL_BLM18P_0603_0-8]  24.36 97.41 270 bottom
FL10  120E  [EMIFIL_BLM15A_0402_0-6]  25.83 95.75 90 bottom
FL11  120E  [EMIFIL_BLM15A_0402_0-6]  71.96 87.83 90 bottom
FL12  120E  [EMIFIL_BLM15A_0402_0-6]  30.56 78.9 90 bottom
FL13  120E  [EMIFIL_BLM15A_0402_0-6]  4.75 63.64 90 bottom
FL14  120E  [EMIFIL_BLM15A_0402_0-6]  20.03 17.43 90 bottom
FL15  120E  [EMIFIL_BLM15A_0402_0-6]  13.54 13.72 270 bottom
J1  CON_PMC_2X20_F  [CON_PMC2X20_QSH-020-01-D-DP-A_S_S_S_3-4]  71.33 146.14 0 top
J2  CON_MINIPCIE_75_F  [CON_MINIPCI75_2199119-4_S_R_S_3-2_2230]  6.49 143.79 90 top
J3  HDR_2X20  [HDR_2X20_PEC20DAAN_S_T_8-6]  9.23 128.2 0 top
J4  CON_BTOB_2X25_M  [CON_BTOB2X25_DF40C-50DP_P_S_S_1-3]  57.87 117.68 90 top
J5  CON_HDMI_1X19_F  [CON_19X1_10029449-001RLF_S_R_S_6-3]  3.57 115.99 270 top
J6  CON_RJ45-14_LPJG16314A4NL  [CON_RJ45-14_LPJG16314A4NL_S_R_T_13-6]  69.42 88.92 90 top
J7  CON_USB-A_4_F  [CON_USBA4_629104151_S_R_S_7-4]  78.01 72.3 90 top
J8  HDR_2X14  [HDR_14X2_100_S_T]  14.31 62.22 180 top
J9  HDR_1X2  [HDR_1X2_61300211121_S_T_8-6]  2.54 62.99 90 top
J10  HDR_1X2  [HDR_1X2_90120-0122_S_T_5-6]  82.46 60 90 top
J11  HDR_2X5  [HDR_2X5_PEC05DAAN_S_T_8-6]  66.3 57.12 180 top
J12  HDR_1X2  [HDR_1X2_90120-0122_S_T_5-6]  64.9 47.65 270 top
J13  CON_USB-C_24_F  [CON_USBC24_2012670_S_R_S_3-9]  3.88 44.95 270 top
J14  CON_AUDIOJACK4_SJ-43514-SMT  [CON_AV4_SJ-43514-SMT_S_R_S_5-1]  76.49 34.78 90 top
J15  CON_USB-C_24_F  [CON_USBC24_2012670_S_R_S_3-9]  3.88 29.95 270 top
J16  HDR_1X2  [HDR_1X2_90120-0122_S_T_5-6]  82.49 27.55 90 top
J17  CON_MUSB-B_5_F  [CON_MUSBB5_629105150521_S_R_S_2-7]  2.7 16.75 270 top
J18  CON_MUSB-B_5_F  [CON_MUSBB5_629105150521_S_R_S_2-7]  82.3 16.75 90 top
J19  HDR_2X10  [HDR_2X10_FTR-110-51-D-06_S_S_8-7]  37.99 10.86 180 top
J20  CON_FLEX_22X1_52435  [CON_FLEX22X1_52435_S_R_S]  71.33 151.77 0 bottom
J21  CON_BOX_2X7_M  [CON_BOX2X7_3020-14-0300-00_P_S_S_10-4]  20.55 146.28 0 bottom
J22  CON_SDCARD9_MEM2051-00-195-00-A  [CON_SD9_MEM2051-00-195-00_S_R_S_2-1]  8.41 98.82 90 bottom
J23  CON_FLEX_40X1_FH12A-40S-0.5SH  [CON_FLEX40X1_FH12A_S_R_S]  64 9.78 180 bottom
L1  0.47uH  [IND1008_1-2]  11.4 86.4 180 top
L2  0.47uH  [IND1008_1-2]  22.58 86.4 0 top
L3  0.47uH  [IND1008_1-2]  9.64 82.2 180 top
L4  90E  [IND4_DLW21H_90X60_SMD_1-4]  66.49 75.9 270 top
L5  0.47uH  [IND1008_1-2]  11.54 73.11 180 top
L6  0.47uH  [IND1008_1-2]  22.58 73.11 0 top
L7  90E  [IND4_DLW21H_90X60_SMD_1-4]  13.54 29.95 180 top
L8  1.5uH  [IND_XFL4020_170X170_SMD_2-1]  23.96 28.15 180 top
L9  0.47uH  [IND0806_1-2]  66.24 85.95 90 bottom
L10  1.8uH  [IND_XAL7070_300X310_SMD_7]  39.11 53.28 90 bottom
L11  10uH  [IND_1277AS-H_130X110_SMD_1-2]  47.71 14.79 0 bottom
LD1  150080VS75000  [LED_150080VS75000_80X50_SMD_0-8]  13.95 108.17 180 top
LD2  150080VS75000  [LED_150080VS75000_80X50_SMD_0-8]  5.82 62.29 270 top
LD3  150080VS75000  [LED_150080VS75000_80X50_SMD_0-8]  51.28 53.58 0 top
LD4  150080VS75000  [LED_150080VS75000_80X50_SMD_0-8]  14.44 51.83 0 top
LD5  150080VS75000  [LED_150080VS75000_80X50_SMD_0-8]  58.35 49.85 270 top
LD6  150080VS75000  [LED_150080VS75000_80X50_SMD_0-8]  13.57 27.73 0 top
LD7  150040VS73220  [LED_150040GS73220_40X20_SMD_0-4]  28.66 23.68 0 top
LD8  150080VS75000  [LED_150080VS75000_80X50_SMD_0-8]  17.71 23.11 180 top
LD9  150080VS75000  [LED_150080VS75000_80X50_SMD_0-8]  49.27 9.08 0 top
LD10  150040RS73220  [LED_150040GS73220_40X20_SMD_0-4]  53.97 6.33 0 top
NOREF  -  []  85 5.08 0 top
NOREF#2  -  []  85 155.18 0 top
NOREF#3  -  [unnamed#2]  75.98 107.38 270 top
NOREF#4  -  [unnamed#2]  2.54 2.54 270 top
NOREF#5  -  [unnamed#2]  78.65 157.72 180 top
NOREF#6  -  [unnamed#2]  6.35 157.72 0 top
NOREF#7  -  []  0 5.08 90 top
NOREF#8  -  [unnamed#2]  4.36 129.47 270 top
NOREF#9  -  [unnamed#2]  3.81 8.89 270 top
NOREF#10  -  []  0 160.26 0 top
NOREF#11  -  []  -7.58 -60.03 0 top
NOREF#12  -  [unnamed#2]  6.35 2.54 0 top
NOREF#13  -  [unnamed#2]  4.36 80.47 270 top
NOREF#14  -  [unnamed#2]  2.54 157.72 270 top
NOREF#15  -  []  0 0 90 top
NOREF#16  -  [unnamed#2]  81.19 129.47 270 top
NOREF#17  -  []  13.61 205.78 0 top
NOREF#18  -  [unnamed#2]  82.46 2.54 90 top
NOREF#19  -  [unnamed#2]  81.19 8.89 270 top
NOREF#20  -  [unnamed#2]  7.53 7.4 180 top
NOREF#21  -  [unnamed#2]  82.46 157.72 90 top
NOREF#22  -  [unnamed#2]  62.36 129.47 270 top
NOREF#23  -  [unnamed#2]  77.43 7.4 180 top
NOREF#24  -  []  2.96 34.71 0 top
NOREF#25  -  [unnamed#2]  77.43 124.19 180 top
NOREF#26  -  [unnamed#2]  77.43 7.4 0 bottom
NOREF#27  -  [unnamed#2]  7.53 7.4 0 bottom
NOREF#28  -  [unnamed#2]  6.35 2.54 180 bottom
NOREF#29  -  [unnamed#2]  6.35 157.72 180 bottom
NOREF#30  -  [unnamed#2]  77.43 124.19 0 bottom
NOREF#31  -  [unnamed#2]  78.65 157.72 0 bottom
Q1  CSD16301Q2  [WSON6_CSD13202Q2_80X80_0-8]  55.96 50.94 0 top
Q2  CSD17575Q3  [VSON8_CSD173_130X130_1-1]  42.45 45.25 90 top
Q3  IRLML6401  [TO_SOT23-123]  47.76 42.17 0 top
Q4  CSD16301Q2  [WSON6_CSD13202Q2_80X80_0-8]  16.28 108.19 180 bottom
Q5  CSD16301Q2  [WSON6_CSD13202Q2_80X80_0-8]  82.6 105.64 90 bottom
Q6  CSD16301Q2  [WSON6_CSD13202Q2_80X80_0-8]  79.51 83.7 90 bottom
Q7  CSD16301Q2  [WSON6_CSD13202Q2_80X80_0-8]  82.17 83.69 90 bottom
Q8  ABC817-40-HF  [SOT23-123_1-2]  3.05 66.81 270 bottom
Q9  CSD16301Q2  [WSON6_CSD13202Q2_80X80_0-8]  16.26 37.58 270 bottom
Q10  CSD25310Q2  [SON6_CSD17313Q2_80X80]  17.12 32.53 90 bottom
Q11  CSD25310Q2  [SON6_CSD17313Q2_80X80]  17.12 29.84 270 bottom
Q12  BSS138LT1G  [SOT23-123_1-2]  27.44 24.71 0 bottom
Q13  IRLML6401  [TO_SOT23-123]  42.52 20.84 180 bottom
Q14  IRLML6401  [TO_SOT23-123]  35.81 20.84 180 bottom
R1  10K  [RES0201_0-5]  51.76 153.83 90 top
R2  10K  [RES0201_0-5]  44.47 153.54 0 top
R3  10K  [RES0201_0-5]  47.05 153.4 180 top
R4  10K  [RES0201_0-5]  56.63 152.56 90 top
R5  10K  [RES0201_0-5]  57.52 152.56 270 top
R6  8.2K_1%  [RES0201_0-5]  45.27 151.97 90 top
R7  10K  [RES0201_0-5]  46.15 151.97 270 top
R8  0E  [RES0201_0-5]  11.88 149.51 270 top
R9  10K  [RES0201_0-5]  40.85 147.89 180 top
R10  0E  [RES0201_0-5]  42.31 147.43 180 top
R11  0E  [RES0201_0-5]  43.63 147.71 270 top
R12  10K  [RES0201_0-5]  44.62 147.71 90 top
R13  10K  [RES0201_0-5]  54.09 147.47 0 top
R14  10K  [RES0201_0-5]  54.09 146.58 180 top
R15  10K  [RES0201_0-5]  44.19 146.36 90 top
R16  10K  [RES0201_0-5]  44.96 146.36 270 top
R17  10K  [RES0201_0-5]  42.31 146.35 0 top
R18  10K  [RES0201_0-5]  47.32 144.35 270 top
R19  8.2K_1%  [RES0201_0-5]  48.3 143.23 180 top
R20  10K  [RES0201_0-5]  50.04 143.34 90 top
R21  10K  [RES0201_0-5]  50.04 141.89 90 top
R22  10K  [RES0201_0-5]  12.16 140.84 90 top
R23  10K_1%  [RES0201_0-5]  46.62 140.8 180 top
R24  0E  [RES0201_0-5]  12.16 139.34 90 top
R25  0E  [RES0201_0-5]  12.92 139.34 90 top
R26  22E_1%  [RES0201_0-5]  56.04 137.69 180 top
R27  22E_1%  [RES0201_0-5]  49.74 137.28 270 top
R28  0E  [RES0201_0-5]  50.51 137.28 270 top
R29  10K  [RES0201_0-5]  40.71 136.5 90 top
R30  4.7K  [RES0201_0-5]  41.47 136.5 90 top
R31  4.7K  [RES0201_0-5]  42.24 136.5 90 top
R32  10K  [RES0201_0-5]  43 136.5 90 top
R33  10K  [RES0201_0-5]  50.14 136.02 180 top
R34  22E_1%  [RES0201_0-5]  59.51 135.62 0 top
R35  22E_1%  [RES0201_0-5]  50.17 134.83 180 top
R36  49.9E_1%  [RES0402_0-5]  47.85 134.34 90 top
R37  22E_1%  [RES0201_0-5]  56.17 133.13 180 top
R38  10K_1%  [RES0402_0-5]  75.49 131.71 180 top
R39  10K_1%  [RES0402_0-5]  75.49 130.44 180 top
R40  10K  [RES0201_0-5]  28.68 125.68 0 top
R41  10K  [RES0201_0-5]  38.92 125.28 180 top
R42  0E  [RES0201_0-5]  25.73 124.84 0 top
R43  0E  [RES0201_0-5]  25.45 124.56 270 top
R44  10K_1%  [RES0201_0-5]  21.14 124.36 90 top
R45  10K  [RES0201_0-5]  17.51 123.83 270 top
R46  10K  [RES0201_0-5]  44.55 123.38 0 top
R47  10K  [RES0201_0-5]  15.55 123.16 180 top
R48  0E  [RES0201_0-5]  26.77 121.76 180 top
R49  10K  [RES0201_0-5]  43.66 119.83 270 top
R50  0E  [RES0402_0-5]  44.79 119.62 270 top
R51  0E  [RES0201_0-5]  39.81 118.04 270 top
R52  0E  [RES0201_0-5]  40.7 118.04 270 top
R53  0E  [RES0201_0-5]  33.96 117.23 270 top
R54  0E  [RES0201_0-5]  14.39 113.99 270 top
R55  0E  [RES0201_0-5]  26.6 112.89 270 top
R56  0E  [RES0201_0-5]  52.33 111.32 90 top
R57  4.7K  [RES0201_0-5]  14.39 111.18 90 top
R58  0E  [RES0201_0-5]  22.09 110.57 0 top
R59  22E_1%  [RES0201_0-5]  23.56 109.94 0 top
R60  0E  [RES0201_0-5]  24.12 109.94 180 top
R61  0E  [RES0402_0-5]  22.19 108.3 0 top
R62  220E  [RES0402_0-5]  11.15 107.68 270 top
R63  10K  [RES0201_0-5]  16.7 107.57 180 top
R64  10K  [RES0201_0-5]  16.65 106.24 180 top
R65  100K_1%  [RES0402_0-5]  14.21 105.72 0 top
R66  0E  [RES0402_0-5]  9.96 105.66 0 top
R67  0E  [RES0201_0-5]  4.63 105.65 180 top
R68  10K_1%  [RES0201_0-5]  3.53 105.42 90 top
R69  0E  [RES0201_0-5]  26.19 105.37 270 top
R70  0E  [RES0201_0-5]  12.54 105.12 180 top
R71  0E  [RES0201_0-5]  25.91 105.09 0 top
R72  0E  [RES0402_0-5]  9.96 104.39 0 top
R73  0E  [RES0201_0-5]  14.37 104.35 270 top
R74  0E  [RES0201_0-5]  25.78 104.04 0 top
R75  0E  [RES0201_0-5]  13.58 103.79 90 top
R76  0E  [RES0201_0-5]  14.37 103.79 90 top
R77  0E  [RES0201_0-5]  26.85 103.76 90 top
R78  0E  [RES0402_0-5]  61.8 103.33 180 top
R79  10K  [RES0201_0-5]  10.83 102.84 0 top
R80  100K_1%  [RES0402_0-5]  22.1 102.45 0 top
R81  0E  [RES0201_0-5]  14.58 102.44 270 top
R82  0E  [RES0201_0-5]  15.45 102.42 270 top
R83  2.49K_1%  [RES0402_0-5]  58.26 102.31 90 top
R84  2.49K_1%  [RES0402_0-5]  59.53 102.31 90 top
R85  2.49K_1%  [RES0402_0-5]  62.13 101.38 90 top
R86  10K  [RES0201_0-5]  63.4 101.17 90 top
R87  10K  [RES0201_0-5]  13.37 101.09 180 top
R88  0E  [RES0201_0-5]  20.29 100.4 0 top
R89  0E  [RES0201_0-5]  21.46 100.12 270 top
R90  10K  [RES0201_0-5]  9.02 99.07 90 top
R91  10K  [RES0201_0-5]  8.21 99.07 90 top
R92  10K  [RES0201_0-5]  7.14 99.07 90 top
R93  2.49K_1%  [RES0402_0-5]  57.35 97.78 180 top
R94  0.01E_1%  [RES_KRL3216T4_1206-4_0-7]  12.84 97.25 90 top
R95  0E  [RES0402_0-5]  22.75 98.26 90 bottom
R96  2.49K_1%  [RES0402_0-5]  57.35 96.51 180 top
R97  10K  [RES0201_0-5]  22.33 94.68 270 top
R98  10K  [RES0201_0-5]  7 94.61 270 top
R99  10K  [RES0201_0-5]  7.92 94.61 270 top
R100  10K  [RES0201_0-5]  8.83 94.61 270 top
R101  0.001E_1%  [RES_CST0612_0612-4_0-9]  17.01 94.49 270 top
R102  0E  [RES0402_0-5]  1.72 94.31 90 top
R103  0E  [RES0402_0-5]  2.87 94.31 90 top
R104  10K  [RES0201_0-5]  4.53 93.54 90 top
R105  0E  [RES0201_0-5]  7.57 92.7 180 top
R106  0E  [RES0201_0-5]  5.64 90.53 180 top
R107  0E  [RES0402_0-5]  60.85 89.8 90 top
R108  0E  [RES0402_0-5]  62.77 89.54 180 top
R109  0E  [RES0201_0-5]  1.68 88.7 270 top
R110  0E  [RES0603_0-75]  24.79 88.69 0 top
R111  49.9K_1%  [RES0201_0-5]  51.88 86.98 270 top
R112  49.9K_1%  [RES0201_0-5]  52.64 86.98 270 top
R113  49.9K_1%  [RES0201_0-5]  53.4 86.98 270 top
R114  49.9K_1%  [RES0201_0-5]  54.16 86.98 270 top
R115  49.9K_1%  [RES0201_0-5]  54.92 86.98 270 top
R116  49.9K_1%  [RES0201_0-5]  55.69 86.98 270 top
R117  49.9K_1%  [RES0201_0-5]  56.45 86.98 270 top
R118  49.9K_1%  [RES0201_0-5]  57.21 86.98 270 top
R119  240E_1%  [RES0402_0-5]  30.89 86.46 0 top
R120  0.01E_1%  [RES_KRL3216T4_1206-4_0-7]  3.77 86.29 90 top
R121  0E  [RES0603_0-75]  74.13 84.12 180 top
R122  240E_1%  [RES0402_0-5]  30.89 84.07 0 top
R123  0E  [RES0201_0-5]  26.62 83.58 180 top
R124  16.5K_1%  [RES0402_0-5]  66.99 83.36 0 top
R125  3.4K_1%  [RES0201_0-5]  68.72 83.36 0 top
R126  10K  [RES0201_0-5]  26.7 82.51 270 top
R127  0E  [RES0201_0-5]  27.3 81.05 90 top
R128  10K  [RES0201_0-5]  64.95 75.86 270 top
R129  10K  [RES0201_0-5]  40.84 75.49 270 top
R130  0E  [RES0201_0-5]  64.95 74.33 270 top
R131  0.001E_1%  [RES_CST0612_0612-4_0-9]  27.87 72.96 180 top
R132  0.01E_1%  [RES_KRL3216T4_1206-4_0-7]  44.88 72.63 0 top
R133  49.9K_1%  [RES0201_0-5]  58.15 70.74 90 top
R134  16.5K_1%  [RES0402_0-5]  52.2 70.23 270 top
R135  3.4K_1%  [RES0201_0-5]  50.83 69.74 180 top
R136  10K  [RES0201_0-5]  62.17 67.86 0 top
R137  0E  [RES0201_0-5]  19.99 67.12 270 top
R138  10K  [RES0402_0-5]  1.51 67.12 270 top
R139  10K  [RES0402_0-5]  2.78 67.12 270 top
R140  100K_1%  [RES0402_0-5]  5.88 65.11 180 top
R141  10K  [RES0201_0-5]  49.55 65 90 top
R142  10K  [RES0201_0-5]  65.33 62.67 180 top
R143  220E  [RES0402_0-5]  7.47 62.24 90 top
R144  10K  [RES0201_0-5]  49.56 61.8 90 top
R145  10K  [RES0201_0-5]  56.66 61.73 270 top
R146  10K  [RES0201_0-5]  65.08 61.5 270 top
R147  10K  [RES0201_0-5]  65.36 59.95 180 top
R148  0E  [RES0201_0-5]  21.67 56.57 90 top
R149  10K  [RES0201_0-5]  9.14 56.21 180 top
R150  220E  [RES0402_0-5]  52.33 55.65 90 top
R151  10K  [RES0201_0-5]  16.94 54.25 0 top
R152  10K  [RES0201_0-5]  76.19 53.86 90 top
R153  10K  [RES0201_0-5]  77.1 53.86 90 top
R154  10K  [RES0201_0-5]  16.94 53.49 180 top
R155  10K  [RES0201_0-5]  22.73 52.76 270 top
R156  10K  [RES0201_0-5]  16.94 52.73 180 top
R157  0E  [RES0603_0-75]  8.45 51.52 0 top
R158  10K  [RES0201_0-5]  19.31 50.4 0 top
R159  1K_1%  [RES0402_0-5]  62.25 50.22 0 top
R160  1K_1%  [RES0402_0-5]  15.24 50.06 0 top
R161  10K  [RES0201_0-5]  19.31 49.49 0 top
R162  220E  [RES0402_0-5]  61.07 48.8 0 top
R163  0E  [RES0402_0-5]  54.46 48.71 180 top
R164  10K  [RES0201_0-5]  56.18 48.71 180 top
R165  4.7K  [RES0201_0-5]  47.63 48.37 90 top
R166  4.7K  [RES0201_0-5]  48.62 48.37 90 top
R167  10K  [RES0201_0-5]  24.74 47.8 270 top
R168  10K  [RES0201_0-5]  62.56 47.65 180 top
R169  0E  [RES0201_0-5]  24.74 46.42 270 top
R170  0E  [RES0201_0-5]  59.4 46.24 180 top
R171  0E  [RES0201_0-5]  60.85 46.24 0 top
R172  10K  [RES0201_0-5]  51.06 45.45 90 top
R173  0E  [RES0201_0-5]  64.66 44.55 0 top
R174  10K  [RES0201_0-5]  61.44 43.72 90 top
R175  10K  [RES0201_0-5]  62.2 43.72 90 top
R176  10K  [RES0201_0-5]  65.22 43.64 0 top
R177  10K  [RES0201_0-5]  56.67 42.11 0 top
R178  0E  [RES0201_0-5]  65.55 41.07 180 top
R179  10K  [RES0201_0-5]  56.95 40.94 270 top
R180  10K  [RES0201_0-5]  61.77 40.24 90 top
R181  10K  [RES0201_0-5]  62.53 40.24 90 top
R182  10K  [RES0201_0-5]  65.55 40.16 0 top
R183  10K  [RES0201_0-5]  47.85 39.05 90 top
R184  4.7K  [RES0201_0-5]  57.6 38.04 0 top
R185  100K  [RES0201_0-5]  45.58 37.12 90 top
R186  100K  [RES0201_0-5]  46.85 37.12 90 top
R187  100K  [RES0201_0-5]  48.12 37.12 90 top
R188  100K  [RES0201_0-5]  49.39 37.12 90 top
R189  100K  [RES0201_0-5]  50.66 37.12 90 top
R190  100K  [RES0201_0-5]  51.93 37.12 90 top
R191  100K  [RES0201_0-5]  53.2 37.12 90 top
R192  100K  [RES0201_0-5]  54.47 37.12 90 top
R193  0E  [RES0603_0-75]  8.45 36.76 0 top
R194  0E  [RES0201_0-5]  64.52 35.62 0 top
R195  130K_1%  [RES0402_0-5]  21.13 35.43 90 top
R196  10K_1%  [RES0201_0-5]  25.49 35.35 0 top
R197  0E  [RES0201_0-5]  24.36 34.87 90 top
R198  0E  [RES0201_0-5]  65.91 34.98 270 top
R199  10K_1%  [RES0201_0-5]  25.49 34.46 180 top
R200  680K_1%  [RES0402_0-5]  20.87 33.72 0 top
R201  0E  [RES0201_0-5]  26.89 33.08 270 top
R202  49.9E_1%  [RES0402_0-5]  68.2 27.08 90 top
R203  1K_1%  [RES0402_0-5]  15.11 26.07 180 top
R204  0E  [RES0201_0-5]  56.68 25.99 90 top
R205  1.1K_1%  [RES0201_0-5]  32.12 25.89 270 top
R206  1.1K_1%  [RES0201_0-5]  33.39 25.89 270 top
R207  1.1K_1%  [RES0201_0-5]  34.66 25.89 270 top
R208  1.1K_1%  [RES0201_0-5]  35.93 25.89 270 top
R209  1.1K_1%  [RES0201_0-5]  37.2 25.89 270 top
R210  1.1K_1%  [RES0201_0-5]  38.47 25.89 270 top
R211  1.1K_1%  [RES0201_0-5]  39.74 25.89 270 top
R212  1.1K_1%  [RES0201_0-5]  41.01 25.89 270 top
R213  1.1K_1%  [RES0201_0-5]  45.58 25.89 270 top
R214  1.1K_1%  [RES0201_0-5]  46.85 25.89 270 top
R215  1.1K_1%  [RES0201_0-5]  48.12 25.89 270 top
R216  1.1K_1%  [RES0201_0-5]  49.39 25.89 270 top
R217  1.1K_1%  [RES0201_0-5]  50.66 25.89 270 top
R218  1.1K_1%  [RES0201_0-5]  51.93 25.89 270 top
R219  1.1K_1%  [RES0201_0-5]  53.2 25.89 270 top
R220  1.1K_1%  [RES0201_0-5]  54.47 25.89 270 top
R221  10K  [RES0201_0-5]  71.27 24.73 90 top
R222  220E  [RES0402_0-5]  30.62 23.68 0 top
R223  10K  [RES0201_0-5]  48.42 23.59 270 top
R224  10K  [RES0201_0-5]  49.34 23.59 270 top
R225  1K_1%  [RES0402_0-5]  72.73 23.44 180 top
R226  0E  [RES0603_0-75]  79.96 22.92 270 top
R227  0E  [RES0805_0-75]  7.12 22.6 180 top
R228  220E  [RES0402_0-5]  20.82 22.49 90 top
R229  1K_1%  [RES0402_0-5]  72.73 22.17 180 top
R230  1K_1%  [RES0402_0-5]  72.73 20.9 180 top
R231  1K_1%  [RES0402_0-5]  72.73 19.63 180 top
R232  4.87K_1%  [RES0402_0-5]  74.82 19.58 0 top
R233  4.7K  [RES0201_0-5]  71.84 13.83 180 top
R234  4.7K  [RES0201_0-5]  71.84 13.07 180 top
R235  10K_1%  [RES0201_0-5]  14.06 10.55 270 top
R236  220E  [RES0402_0-5]  52.31 8.93 180 top
R237  30K  [RES0402_0-5]  50.2 7.26 0 top
R238  20K_1%  [RES0402_0-5]  51.98 7.15 270 top
R239  4.7K  [RES0201_0-5]  70.3 6.88 0 top
R240  220E  [RES0402_0-5]  56.08 6.33 180 top
R241  10K_1%  [RES0201_0-5]  26.18 152.81 90 bottom
R242  49.9K_1%  [RES0201_0-5]  25.32 152.81 90 bottom
R243  0E  [RES0201_0-5]  24.55 152.81 270 bottom
R244  0E  [RES0201_0-5]  23.37 152.53 180 bottom
R245  1K_1%  [RES0402_0-5]  58.37 152.34 90 bottom
R246  4.7K  [RES0201_0-5]  56.87 151.06 270 bottom
R247  0E  [RES0402_0-5]  59.64 150.31 90 bottom
R248  0E  [RES0402_0-5]  58.37 150.31 90 bottom
R249  4.7K  [RES0201_0-5]  56.87 147.94 90 bottom
R250  10K  [RES0201_0-5]  6.37 148.08 180 bottom
R251  10K_1%  [RES0402_0-5]  60.74 146.74 0 bottom
R252  10K  [RES0201_0-5]  45.03 146.24 90 bottom
R253  10K  [RES0201_0-5]  44.27 146.24 270 bottom
R254  33E  [RES0201_0-5]  6.47 142.64 90 bottom
R255  49.9K_1%  [RES0402_0-5]  53.45 143.42 0 bottom
R256  100K_1%  [RES0402_0-5]  50.12 141.9 180 bottom
R257  0E  [RES0201_0-5]  27.89 140.04 180 bottom
R258  0E  [RES0201_0-5]  25.35 140.04 180 bottom
R259  0E  [RES0201_0-5]  17.73 140.04 180 bottom
R260  0E  [RES0201_0-5]  15.19 140.04 180 bottom
R261  0E  [RES0201_0-5]  12.65 140.04 180 bottom
R262  10K_1%  [RES0201_0-5]  5.62 140.04 0 bottom
R263  10K  [RES0201_0-5]  20.37 37.71 180 top
R264  0E  [RES0201_0-5]  23.22 139.36 270 bottom
R265  0E  [RES0201_0-5]  27.89 139.26 180 bottom
R266  0E  [RES0201_0-5]  25.35 139.26 180 bottom
R267  0E  [RES0201_0-5]  17.73 139.26 180 bottom
R268  0E  [RES0201_0-5]  15.19 139.26 180 bottom
R269  0E  [RES0201_0-5]  12.65 139.26 180 bottom
R270  0E  [RES0201_0-5]  6.72 138.68 180 bottom
R271  100K  [RES0201_0-5]  5.51 138.64 270 bottom
R272  0E  [RES0201_0-5]  22.33 139.36 270 bottom
R273  10K_1%  [RES0201_0-5]  27.61 138.08 270 bottom
R274  10K_1%  [RES0201_0-5]  25.07 138.08 270 bottom
R275  10K_1%  [RES0201_0-5]  17.45 138.08 270 bottom
R276  10K_1%  [RES0201_0-5]  14.91 138.08 270 bottom
R277  10K_1%  [RES0201_0-5]  12.37 138.08 270 bottom
R278  4.7K  [RES0201_0-5]  44.07 136.53 90 bottom
R279  4.7K  [RES0201_0-5]  43.31 136.53 90 bottom
R280  22E_1%  [RES0201_0-5]  20.03 136.49 270 bottom
R281  4.7K  [RES0201_0-5]  4.62 136 270 bottom
R282  0E  [RES0201_0-5]  20.03 135.93 90 bottom
R283  10K  [RES0201_0-5]  24.02 36.18 90 top
R284  10K  [RES0201_0-5]  60.74 135.14 180 bottom
R285  10K  [RES0201_0-5]  25.32 36.52 0 top
R286  100K  [RES0201_0-5]  15.39 134.25 90 bottom
R287  10K  [RES0201_0-5]  22.05 133.17 270 bottom
R288  10K  [RES0201_0-5]  21.16 133.17 270 bottom
R289  10K  [RES0201_0-5]  39.71 132.69 270 bottom
R290  10K  [RES0201_0-5]  37.17 132.69 270 bottom
R291  10K  [RES0201_0-5]  52.13 132.41 0 bottom
R292  10K_1%  [RES0402_0-5]  65.94 129.62 90 bottom
R293  4.7K  [RES0201_0-5]  14.31 126.26 90 bottom
R294  4.7K  [RES0201_0-5]  11.77 126.26 90 bottom
R295  10K  [RES0201_0-5]  51.35 125.23 90 bottom
R296  10K  [RES0201_0-5]  50.35 125.23 90 bottom
R297  10K  [RES0201_0-5]  49.35 125.23 90 bottom
R298  2.2K  [RES0402_0-5]  18.5 124.08 270 bottom
R299  10K  [RES0201_0-5]  48.78 123.98 135 bottom
R300  10K  [RES0201_0-5]  47.74 123.68 90 bottom
R301  10K  [RES0201_0-5]  45.79 123.12 270 bottom
R302  10K  [RES0201_0-5]  50.85 123.01 0 bottom
R303  10K  [RES0201_0-5]  47.63 122.19 180 bottom
R304  10K  [RES0201_0-5]  50.95 121.86 315 bottom
R305  1.1K_1%  [RES0201_0-5]  49.76 121.38 270 bottom
